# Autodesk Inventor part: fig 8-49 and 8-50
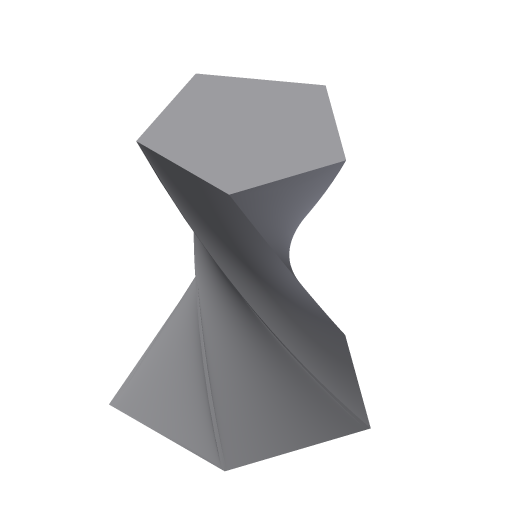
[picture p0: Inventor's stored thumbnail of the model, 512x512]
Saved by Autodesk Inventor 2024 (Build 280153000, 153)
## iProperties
Shininess: 64.0
Length Units: 11269
Angle Units: 11279
Time Units: 11290
Mass Units: 11283
Length Display Precision: 3
Angle Display Precision: 2
Compacted: True
Part Number: fig 8-49 and 8-50
Document SubType Name: Modeling
Created: 2002-12
Designer: deepak
Density: 1 g/cm^3
Material: Generic
Appearance: Default
Density: 0.0
Volumn: 0.0
Area: 0.0
PropertySet Name: Model Information
Control State: 0
Master: False
Checked Out: False
Author: deepak
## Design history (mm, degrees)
sketch "Sketch1"
  geometry: L1 (0, 21.819)-(20.751, 6.743); L2 (20.751, 6.743)-(12.825, -17.652); L3 (12.825, -17.652)-(-12.825, -17.652); L4 (-12.825, -17.652)-(-20.751, 6.743); L5 (-20.751, 6.743)-(0, 21.819); 1 further point
  constraints: 10 end point, 9 other
workplane "Work Plane1"
sketch "Sketch2"
  geometry: L1 (0, 8.24)-(7.836, 2.546); L2 (7.836, 2.546)-(4.843, -6.666); L3 (4.843, -6.666)-(-4.843, -6.666); L4 (-4.843, -6.666)-(-7.836, 2.546); L5 (-7.836, 2.546)-(0, 8.24); 1 further point
  constraints: 10 end point, 9 other
workplane "Work Plane2"
sketch "Sketch3"
  geometry: L1 (0, 17.494)-(16.637, 5.406); L2 (16.637, 5.406)-(10.283, -14.153); L3 (10.283, -14.153)-(-10.283, -14.153); L4 (-10.283, -14.153)-(-16.637, 5.406); L5 (-16.637, 5.406)-(0, 17.494); 1 further point
  constraints: 10 end point, 9 other
loft "Loft4" sketch "Sketch3" dims "d20" = 0, "d21" = 90 deg, "d22" = 0, "d23" = 90 deg, "d24" = 0, "d25" = 90 deg
body "Solid1"
other parameters: "d0" = 25, "d1" = 25
